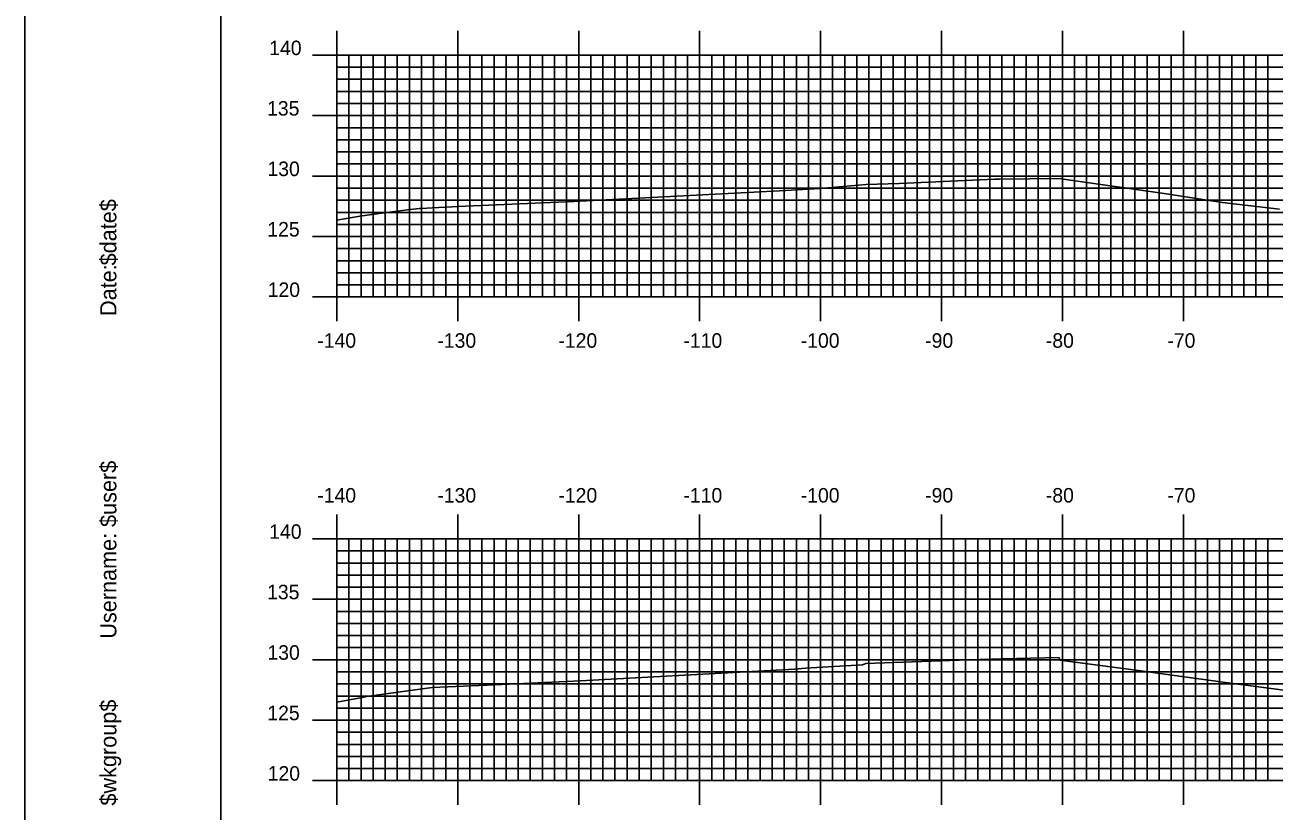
# Model space of a CAD drawing. Extents: x 841388 to 841731, y 363538 to 363758.
# Drawn here: x 841388.1 to 841491.4, y 363633.2 to 363698.2 of the extents above; entities that cross this region are included whole.
import ezdxf

# ---------------------------------------------------------------- set-up
doc = ezdxf.new("R2010")
doc.units = 0
for name, color, linetype in [('BORDER', 7, 'Continuous'), ('H_V ANNOTATION', 7, 'Continuous'), ('M_Roadway_Centerline', 7, 'Continuous'), ('MAJOR', 7, 'Continuous'), ('MINOR', 7, 'Continuous'), ('PLOT BOUNDARY', 7, 'Continuous'), ('S_Roadway_Centerline', 7, 'Continuous')]:
    doc.layers.add(name, color=color, linetype=linetype)

msp = doc.modelspace()

# ---------------------------------------------------------------- linework, layer by layer
at = {"layer": 'BORDER'}
msp.add_lwpolyline([(841404.26, 363543.72), (841724.26, 363543.72), (841724.26, 363753.72), (841404.26, 363753.72)], close=True, dxfattribs=at)
at = {"layer": 'MAJOR'}
for p, q in [((841413.86, 363697.73), (841413.86, 363695.72)), ((841423.86, 363697.73), (841423.86, 363695.72)), ((841433.86, 363697.73), (841433.86, 363695.72)), ((841443.86, 363697.73), (841443.86, 363695.72)), ((841453.86, 363697.73), (841453.86, 363695.72)), ((841463.86, 363697.73), (841463.86, 363695.72)), ((841473.86, 363697.73), (841473.86, 363695.72)), ((841483.86, 363697.73), (841483.86, 363695.72)), ((841411.85, 363695.72), (841413.86, 363695.72)), ((841413.86, 363695.72), (841693.86, 363695.72)), ((841413.86, 363675.72), (841413.86, 363695.72)), ((841413.86, 363675.72), (841413.86, 363695.72)), ((841413.86, 363695.72), (841693.86, 363695.72)), ((841423.86, 363675.72), (841423.86, 363695.72)), ((841433.86, 363675.72), (841433.86, 363695.72)), ((841443.86, 363675.72), (841443.86, 363695.72)), ((841453.86, 363675.72), (841453.86, 363695.72)), ((841463.86, 363675.72), (841463.86, 363695.72)), ((841473.86, 363675.72), (841473.86, 363695.72)), ((841483.86, 363675.72), (841483.86, 363695.72)), ((841411.85, 363690.72), (841413.86, 363690.72)), ((841413.86, 363690.72), (841693.86, 363690.72)), ((841411.85, 363685.72), (841413.86, 363685.72)), ((841413.86, 363685.72), (841693.86, 363685.72)), ((841411.85, 363680.72), (841413.86, 363680.72)), ((841413.86, 363680.72), (841693.86, 363680.72)), ((841411.85, 363675.72), (841413.86, 363675.72)), ((841413.86, 363675.72), (841693.86, 363675.72)), ((841413.86, 363675.72), (841693.86, 363675.72)), ((841413.86, 363673.72), (841413.86, 363675.72)), ((841423.86, 363673.72), (841423.86, 363675.72)), ((841433.86, 363673.72), (841433.86, 363675.72)), ((841443.86, 363673.72), (841443.86, 363675.72)), ((841453.86, 363673.72), (841453.86, 363675.72)), ((841463.86, 363673.72), (841463.86, 363675.72)), ((841473.86, 363673.72), (841473.86, 363675.72)), ((841483.86, 363673.72), (841483.86, 363675.72)), ((841413.86, 363657.73), (841413.86, 363655.72)), ((841423.86, 363657.73), (841423.86, 363655.72)), ((841433.86, 363657.73), (841433.86, 363655.72)), ((841443.86, 363657.73), (841443.86, 363655.72)), ((841453.86, 363657.73), (841453.86, 363655.72)), ((841463.86, 363657.73), (841463.86, 363655.72)), ((841473.86, 363657.73), (841473.86, 363655.72)), ((841483.86, 363657.73), (841483.86, 363655.72)), ((841411.85, 363655.72), (841413.86, 363655.72)), ((841413.86, 363655.72), (841693.86, 363655.72)), ((841413.86, 363635.72), (841413.86, 363655.72)), ((841413.86, 363635.72), (841413.86, 363655.72)), ((841413.86, 363655.72), (841693.86, 363655.72)), ((841423.86, 363635.72), (841423.86, 363655.72)), ((841433.86, 363635.72), (841433.86, 363655.72)), ((841443.86, 363635.72), (841443.86, 363655.72)), ((841453.86, 363635.72), (841453.86, 363655.72)), ((841463.86, 363635.72), (841463.86, 363655.72)), ((841473.86, 363635.72), (841473.86, 363655.72)), ((841483.86, 363635.72), (841483.86, 363655.72)), ((841411.85, 363650.72), (841413.86, 363650.72)), ((841413.86, 363650.72), (841693.86, 363650.72)), ((841411.85, 363645.72), (841413.86, 363645.72)), ((841413.86, 363645.72), (841693.86, 363645.72)), ((841411.85, 363640.72), (841413.86, 363640.72)), ((841413.86, 363640.72), (841693.86, 363640.72)), ((841411.85, 363635.72), (841413.86, 363635.72)), ((841413.86, 363635.72), (841693.86, 363635.72)), ((841413.86, 363635.72), (841693.86, 363635.72)), ((841413.86, 363633.72), (841413.86, 363635.72)), ((841423.86, 363633.72), (841423.86, 363635.72)), ((841433.86, 363633.72), (841433.86, 363635.72)), ((841443.86, 363633.72), (841443.86, 363635.72)), ((841453.86, 363633.72), (841453.86, 363635.72)), ((841463.86, 363633.72), (841463.86, 363635.72)), ((841473.86, 363633.72), (841473.86, 363635.72)), ((841483.86, 363633.72), (841483.86, 363635.72))]:
    msp.add_line(p, q, dxfattribs=at)
at = {"layer": 'MINOR'}
for p, q in [((841414.86, 363675.72), (841414.86, 363695.72)), ((841415.86, 363675.72), (841415.86, 363695.72)), ((841416.86, 363675.72), (841416.86, 363695.72)), ((841417.86, 363675.72), (841417.86, 363695.72)), ((841418.86, 363675.72), (841418.86, 363695.72)), ((841419.86, 363675.72), (841419.86, 363695.72)), ((841420.86, 363675.72), (841420.86, 363695.72)), ((841421.86, 363675.72), (841421.86, 363695.72)), ((841422.86, 363675.72), (841422.86, 363695.72)), ((841424.86, 363675.72), (841424.86, 363695.72)), ((841425.86, 363675.72), (841425.86, 363695.72)), ((841426.86, 363675.72), (841426.86, 363695.72)), ((841427.86, 363675.72), (841427.86, 363695.72)), ((841428.86, 363675.72), (841428.86, 363695.72)), ((841429.86, 363675.72), (841429.86, 363695.72)), ((841430.86, 363675.72), (841430.86, 363695.72)), ((841431.86, 363675.72), (841431.86, 363695.72)), ((841432.86, 363675.72), (841432.86, 363695.72)), ((841434.86, 363675.72), (841434.86, 363695.72)), ((841435.86, 363675.72), (841435.86, 363695.72)), ((841436.86, 363675.72), (841436.86, 363695.72)), ((841437.86, 363675.72), (841437.86, 363695.72)), ((841438.86, 363675.72), (841438.86, 363695.72)), ((841439.86, 363675.72), (841439.86, 363695.72)), ((841440.86, 363675.72), (841440.86, 363695.72)), ((841441.86, 363675.72), (841441.86, 363695.72)), ((841442.86, 363675.72), (841442.86, 363695.72)), ((841444.86, 363675.72), (841444.86, 363695.72)), ((841445.86, 363675.72), (841445.86, 363695.72)), ((841446.86, 363675.72), (841446.86, 363695.72)), ((841447.86, 363675.72), (841447.86, 363695.72)), ((841448.86, 363675.72), (841448.86, 363695.72)), ((841449.86, 363675.72), (841449.86, 363695.72)), ((841450.86, 363675.72), (841450.86, 363695.72)), ((841451.86, 363675.72), (841451.86, 363695.72)), ((841452.86, 363675.72), (841452.86, 363695.72)), ((841454.86, 363675.72), (841454.86, 363695.72)), ((841455.86, 363675.72), (841455.86, 363695.72)), ((841456.86, 363675.72), (841456.86, 363695.72)), ((841457.86, 363675.72), (841457.86, 363695.72)), ((841458.86, 363675.72), (841458.86, 363695.72)), ((841459.86, 363675.72), (841459.86, 363695.72)), ((841460.86, 363675.72), (841460.86, 363695.72)), ((841461.86, 363675.72), (841461.86, 363695.72)), ((841462.86, 363675.72), (841462.86, 363695.72)), ((841464.86, 363675.72), (841464.86, 363695.72)), ((841465.86, 363675.72), (841465.86, 363695.72)), ((841466.86, 363675.72), (841466.86, 363695.72)), ((841467.86, 363675.72), (841467.86, 363695.72)), ((841468.86, 363675.72), (841468.86, 363695.72)), ((841469.86, 363675.72), (841469.86, 363695.72)), ((841470.86, 363675.72), (841470.86, 363695.72)), ((841471.86, 363675.72), (841471.86, 363695.72)), ((841472.86, 363675.72), (841472.86, 363695.72)), ((841474.86, 363675.72), (841474.86, 363695.72)), ((841475.86, 363675.72), (841475.86, 363695.72)), ((841476.86, 363675.72), (841476.86, 363695.72)), ((841477.86, 363675.72), (841477.86, 363695.72)), ((841478.86, 363675.72), (841478.86, 363695.72)), ((841479.86, 363675.72), (841479.86, 363695.72)), ((841480.86, 363675.72), (841480.86, 363695.72)), ((841481.86, 363675.72), (841481.86, 363695.72)), ((841482.86, 363675.72), (841482.86, 363695.72)), ((841484.86, 363675.72), (841484.86, 363695.72)), ((841485.86, 363675.72), (841485.86, 363695.72)), ((841486.86, 363675.72), (841486.86, 363695.72)), ((841487.86, 363675.72), (841487.86, 363695.72)), ((841488.86, 363675.72), (841488.86, 363695.72)), ((841489.86, 363675.72), (841489.86, 363695.72)), ((841490.86, 363675.72), (841490.86, 363695.72)), ((841413.86, 363694.72), (841693.86, 363694.72)), ((841413.86, 363694.72), (841415.86, 363694.72)), ((841413.86, 363693.72), (841693.86, 363693.72)), ((841413.86, 363693.72), (841415.86, 363693.72)), ((841413.86, 363692.72), (841693.86, 363692.72)), ((841413.86, 363692.72), (841415.86, 363692.72)), ((841413.86, 363691.72), (841693.86, 363691.72)), ((841413.86, 363691.72), (841415.86, 363691.72)), ((841413.86, 363689.72), (841693.86, 363689.72)), ((841413.86, 363689.72), (841415.86, 363689.72)), ((841413.86, 363688.72), (841693.86, 363688.72)), ((841413.86, 363688.72), (841415.86, 363688.72)), ((841413.86, 363687.72), (841693.86, 363687.72)), ((841413.86, 363687.72), (841415.86, 363687.72)), ((841413.86, 363686.72), (841693.86, 363686.72)), ((841413.86, 363686.72), (841415.86, 363686.72)), ((841413.86, 363684.72), (841693.86, 363684.72)), ((841413.86, 363684.72), (841415.86, 363684.72)), ((841413.86, 363683.72), (841693.86, 363683.72)), ((841413.86, 363683.72), (841415.86, 363683.72)), ((841413.86, 363682.72), (841693.86, 363682.72)), ((841413.86, 363682.72), (841415.86, 363682.72)), ((841413.86, 363681.72), (841693.86, 363681.72)), ((841413.86, 363681.72), (841415.86, 363681.72)), ((841413.86, 363679.72), (841693.86, 363679.72)), ((841413.86, 363679.72), (841415.86, 363679.72)), ((841413.86, 363678.72), (841693.86, 363678.72)), ((841413.86, 363678.72), (841415.86, 363678.72)), ((841413.86, 363677.72), (841693.86, 363677.72)), ((841413.86, 363677.72), (841415.86, 363677.72)), ((841413.86, 363676.72), (841693.86, 363676.72)), ((841413.86, 363676.72), (841415.86, 363676.72)), ((841414.86, 363635.72), (841414.86, 363655.72)), ((841415.86, 363635.72), (841415.86, 363655.72)), ((841416.86, 363635.72), (841416.86, 363655.72)), ((841417.86, 363635.72), (841417.86, 363655.72)), ((841418.86, 363635.72), (841418.86, 363655.72)), ((841419.86, 363635.72), (841419.86, 363655.72)), ((841420.86, 363635.72), (841420.86, 363655.72)), ((841421.86, 363635.72), (841421.86, 363655.72)), ((841422.86, 363635.72), (841422.86, 363655.72)), ((841424.86, 363635.72), (841424.86, 363655.72)), ((841425.86, 363635.72), (841425.86, 363655.72)), ((841426.86, 363635.72), (841426.86, 363655.72)), ((841427.86, 363635.72), (841427.86, 363655.72)), ((841428.86, 363635.72), (841428.86, 363655.72)), ((841429.86, 363635.72), (841429.86, 363655.72)), ((841430.86, 363635.72), (841430.86, 363655.72)), ((841431.86, 363635.72), (841431.86, 363655.72)), ((841432.86, 363635.72), (841432.86, 363655.72)), ((841434.86, 363635.72), (841434.86, 363655.72)), ((841435.86, 363635.72), (841435.86, 363655.72)), ((841436.86, 363635.72), (841436.86, 363655.72)), ((841437.86, 363635.72), (841437.86, 363655.72)), ((841438.86, 363635.72), (841438.86, 363655.72)), ((841439.86, 363635.72), (841439.86, 363655.72)), ((841440.86, 363635.72), (841440.86, 363655.72)), ((841441.86, 363635.72), (841441.86, 363655.72)), ((841442.86, 363635.72), (841442.86, 363655.72)), ((841444.86, 363635.72), (841444.86, 363655.72)), ((841445.86, 363635.72), (841445.86, 363655.72)), ((841446.86, 363635.72), (841446.86, 363655.72)), ((841447.86, 363635.72), (841447.86, 363655.72)), ((841448.86, 363635.72), (841448.86, 363655.72)), ((841449.86, 363635.72), (841449.86, 363655.72)), ((841450.86, 363635.72), (841450.86, 363655.72)), ((841451.86, 363635.72), (841451.86, 363655.72)), ((841452.86, 363635.72), (841452.86, 363655.72)), ((841454.86, 363635.72), (841454.86, 363655.72)), ((841455.86, 363635.72), (841455.86, 363655.72)), ((841456.86, 363635.72), (841456.86, 363655.72)), ((841457.86, 363635.72), (841457.86, 363655.72)), ((841458.86, 363635.72), (841458.86, 363655.72)), ((841459.86, 363635.72), (841459.86, 363655.72)), ((841460.86, 363635.72), (841460.86, 363655.72)), ((841461.86, 363635.72), (841461.86, 363655.72)), ((841462.86, 363635.72), (841462.86, 363655.72)), ((841464.86, 363635.72), (841464.86, 363655.72)), ((841465.86, 363635.72), (841465.86, 363655.72)), ((841466.86, 363635.72), (841466.86, 363655.72)), ((841467.86, 363635.72), (841467.86, 363655.72)), ((841468.86, 363635.72), (841468.86, 363655.72)), ((841469.86, 363635.72), (841469.86, 363655.72)), ((841470.86, 363635.72), (841470.86, 363655.72)), ((841471.86, 363635.72), (841471.86, 363655.72)), ((841472.86, 363635.72), (841472.86, 363655.72)), ((841474.86, 363635.72), (841474.86, 363655.72)), ((841475.86, 363635.72), (841475.86, 363655.72)), ((841476.86, 363635.72), (841476.86, 363655.72)), ((841477.86, 363635.72), (841477.86, 363655.72)), ((841478.86, 363635.72), (841478.86, 363655.72)), ((841479.86, 363635.72), (841479.86, 363655.72)), ((841480.86, 363635.72), (841480.86, 363655.72)), ((841481.86, 363635.72), (841481.86, 363655.72)), ((841482.86, 363635.72), (841482.86, 363655.72)), ((841484.86, 363635.72), (841484.86, 363655.72)), ((841485.86, 363635.72), (841485.86, 363655.72)), ((841486.86, 363635.72), (841486.86, 363655.72)), ((841487.86, 363635.72), (841487.86, 363655.72)), ((841488.86, 363635.72), (841488.86, 363655.72)), ((841489.86, 363635.72), (841489.86, 363655.72)), ((841490.86, 363635.72), (841490.86, 363655.72)), ((841413.86, 363654.72), (841693.86, 363654.72)), ((841413.86, 363654.72), (841415.86, 363654.72)), ((841413.86, 363653.72), (841693.86, 363653.72)), ((841413.86, 363653.72), (841415.86, 363653.72)), ((841413.86, 363652.72), (841693.86, 363652.72)), ((841413.86, 363652.72), (841415.86, 363652.72)), ((841413.86, 363651.72), (841693.86, 363651.72)), ((841413.86, 363651.72), (841415.86, 363651.72)), ((841413.86, 363649.72), (841693.86, 363649.72)), ((841413.86, 363649.72), (841415.86, 363649.72)), ((841413.86, 363648.72), (841693.86, 363648.72)), ((841413.86, 363648.72), (841415.86, 363648.72)), ((841413.86, 363647.72), (841693.86, 363647.72)), ((841413.86, 363647.72), (841415.86, 363647.72)), ((841413.86, 363646.72), (841693.86, 363646.72)), ((841413.86, 363646.72), (841415.86, 363646.72)), ((841413.86, 363644.72), (841693.86, 363644.72)), ((841413.86, 363644.72), (841415.86, 363644.72)), ((841413.86, 363643.72), (841693.86, 363643.72)), ((841413.86, 363643.72), (841415.86, 363643.72)), ((841413.86, 363642.72), (841693.86, 363642.72)), ((841413.86, 363642.72), (841415.86, 363642.72)), ((841413.86, 363641.72), (841693.86, 363641.72)), ((841413.86, 363641.72), (841415.86, 363641.72)), ((841413.86, 363639.72), (841693.86, 363639.72)), ((841413.86, 363639.72), (841415.86, 363639.72)), ((841413.86, 363638.72), (841693.86, 363638.72)), ((841413.86, 363638.72), (841415.86, 363638.72)), ((841413.86, 363637.72), (841693.86, 363637.72)), ((841413.86, 363637.72), (841415.86, 363637.72)), ((841413.86, 363636.72), (841693.86, 363636.72)), ((841413.86, 363636.72), (841415.86, 363636.72))]:
    msp.add_line(p, q, dxfattribs=at)
at = {"layer": 'PLOT BOUNDARY'}
msp.add_lwpolyline([(841388.07, 363537.6), (841728.07, 363537.6), (841728.07, 363757.6), (841388.07, 363757.6)], close=True, dxfattribs=at)
at = {"layer": 'S_Roadway_Centerline'}
for points in [[(841413.86, 363682.08), (841415.77, 363682.41), (841417.17, 363682.6), (841419.7, 363682.93), (841420.68, 363683.04), (841420.88, 363683.05), (841421.75, 363683.09), (841424.51, 363683.22), (841433.47, 363683.62), (841440.94, 363684.01), (841451, 363684.52), (841453.82, 363684.69), (841457.64, 363685.01), (841460.35, 363685.1), (841468.25, 363685.46), (841468.66, 363685.47), (841473.67, 363685.51), (841473.95, 363685.46), (841482.27, 363684.27), (841487.08, 363683.53), (841491.81, 363682.99)], [(841413.86, 363642.21), (841415.96, 363642.61), (841416.3, 363642.68), (841421.74, 363643.42), (841426.93, 363643.65), (841434, 363643.98), (841449.19, 363644.81), (841451.71, 363644.95), (841452.62, 363645.01), (841457.33, 363645.31), (841457.6, 363645.4), (841466.1, 363645.7), (841468.93, 363645.79), (841473.59, 363645.9), (841473.65, 363645.69), (841479.93, 363644.86), (841487.35, 363643.84), (841494.89, 363642.85)]]:
    msp.add_lwpolyline(points, dxfattribs=at)

# ---------------------------------------------------------------- texts
at = {"layer": 'BORDER'}
for s, p in [('$date$', (841395.63, 363678.33)), ('Date:', (841395.63, 363674.15)), ('$user$', (841395.63, 363656.7)), ('Username:', (841395.63, 363647.46)), ('$wkgroup$', (841395.63, 363633.66))]:
    msp.add_text(s, height=1.339, rotation=90, dxfattribs=at).set_placement(p)
at = {"layer": 'H_V ANNOTATION'}
for s, p in [('140', (841408.27, 363695.72)), ('135', (841408.09, 363690.72)), ('130', (841408.12, 363685.72)), ('125', (841408.11, 363680.72)), ('120', (841408.14, 363675.72)), ('-140', (841412.24, 363671.52)), ('-130', (841422.17, 363671.52)), ('-120', (841432.18, 363671.52)), ('-110', (841442.52, 363671.52)), ('-100', (841452.22, 363671.52)), ('-90', (841462.51, 363671.52)), ('-80', (841472.49, 363671.52)), ('-70', (841482.54, 363671.52)), ('-140', (841412.24, 363658.72)), ('-130', (841422.17, 363658.72)), ('-120', (841432.18, 363658.72)), ('-110', (841442.52, 363658.72)), ('-100', (841452.22, 363658.72)), ('-90', (841462.51, 363658.72)), ('-80', (841472.49, 363658.72)), ('-70', (841482.54, 363658.72)), ('140', (841408.27, 363655.72)), ('135', (841408.09, 363650.72)), ('130', (841408.12, 363645.72)), ('125', (841408.11, 363640.72)), ('120', (841408.14, 363635.72))]:
    msp.add_text(s, height=1.2, dxfattribs=at).set_placement(p)
at = {"layer": 'M_Roadway_Centerline'}
for s, p in [('C', (841457.64, 363685.01)), ('L', (841457.64, 363685.01)), ('C', (841457.6, 363645.4)), ('L', (841457.6, 363645.39))]:
    msp.add_text(s, height=0.0146, dxfattribs=at).set_placement(p)
at = {"layer": 'MAJOR'}
for p in [(841413.85, 363675.72), (841413.85, 363635.72)]:
    msp.add_text('-', height=0.012, dxfattribs=at).set_placement(p)

doc.saveas('drawing.dxf')
